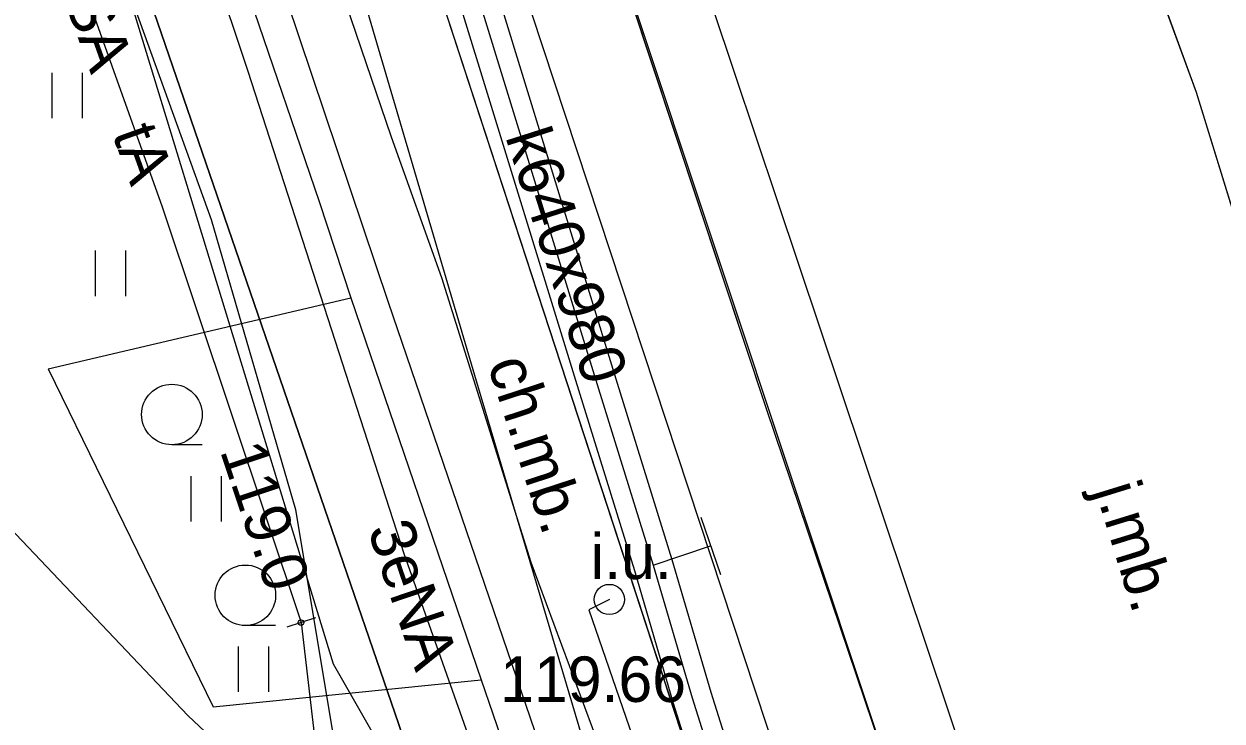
# Model space of a CAD drawing. Extents: x 6432121 to 6432331, y 5662538 to 5662686.
# Drawn here: x 6432255.02 to 6432274.79, y 5662593.95 to 5662605.46 of the extents above; entities that cross this region are included whole.
import ezdxf

# ---------------------------------------------------------------- set-up
doc = ezdxf.new("R2010")
doc.units = 0
for name, color, linetype in [('Warstwa 1', 7, 'Continuous'), ('Warstwa 10', 7, 'Continuous'), ('Warstwa 11', 7, 'Continuous'), ('Warstwa 12', 7, 'Continuous'), ('Warstwa 13', 7, 'Continuous'), ('Warstwa 14', 7, 'Continuous'), ('Warstwa 15', 7, 'Continuous'), ('Warstwa 19', 7, 'Continuous'), ('Warstwa 20', 7, 'Continuous'), ('Warstwa 24', 7, 'Continuous'), ('Warstwa 37', 7, 'Continuous'), ('Warstwa 5', 7, 'Continuous'), ('Warstwa 6', 7, 'Continuous'), ('Warstwa 61', 7, 'Continuous'), ('Warstwa 8', 7, 'Continuous'), ('Warstwa 9', 7, 'Continuous')]:
    doc.layers.add(name, color=color, linetype=linetype)

msp = doc.modelspace()

# ---------------------------------------------------------------- linework, layer by layer
at = {"layer": 'Warstwa 1'}
msp.add_line((6432246.69, 5662636.13), (6432263.163, 5662588.197), dxfattribs=at)
msp.add_line((6432246.69, 5662636.13), (6432263.163, 5662588.197), dxfattribs=at)
at = {"layer": 'Warstwa 10'}
for points in [[(6432244.8, 5662632.18), (6432245.33, 5662629.54), (6432245.69, 5662629.01), (6432246.09, 5662628.79), (6432247.73, 5662627.49), (6432248.93, 5662625.88), (6432257.3, 5662602.44), (6432259.59, 5662595.58)], [(6432259.59, 5662595.58), (6432260.12, 5662591.05), (6432259.44, 5662584.94), (6432258.97, 5662582.4)]]:
    msp.add_lwpolyline(points, dxfattribs=at)
at = {"layer": 'Warstwa 12'}
for points in [[(6432260.149, 5662593.584), (6432259.505, 5662597.442), (6432258.113, 5662602.229), (6432246.261, 5662635.045), (6432242.6, 5662639.91), (6432237.105, 5662644.467), (6432235.235, 5662651.91), (6432228.3, 5662671.335), (6432227.148, 5662676.149), (6432227.614, 5662677.443), (6432228.191, 5662677.996), (6432231.551, 5662678.816), (6432233.235, 5662681.053)], [(6432244.451, 5662661.055), (6432244.51, 5662660.562), (6432244.747, 5662659.597), (6432247.148, 5662651.498), (6432250.159, 5662641.297), (6432254.564, 5662626.481), (6432257.548, 5662616.394), (6432260.807, 5662605.248), (6432262.453, 5662599.664), (6432266.272, 5662586.802), (6432268.265, 5662580.011), (6432268.423, 5662579.446)], [(6432243.958, 5662654.289), (6432246.621, 5662646.365), (6432250.032, 5662636.381), (6432251.998, 5662630.56), (6432253.864, 5662624.956), (6432256.122, 5662618.174), (6432258.071, 5662612.417), (6432261.076, 5662603.597), (6432261.907, 5662601.278), (6432263.382, 5662596.576), (6432264.52, 5662593.503), (6432265.328, 5662591.162), (6432268.156, 5662582.752), (6432268.733, 5662580.715)], [(6432243.16, 5662653.357), (6432252.465, 5662626.114), (6432254.893, 5662619.007), (6432257.883, 5662610.233), (6432261.03, 5662600.869), (6432263.754, 5662592.896), (6432267.107, 5662583.22), (6432267.857, 5662579.356), (6432269.061, 5662572.854)], [(6432244.8, 5662632.18), (6432245.33, 5662629.54), (6432245.69, 5662629.01), (6432246.09, 5662628.79), (6432247.73, 5662627.49), (6432248.93, 5662625.88), (6432257.3, 5662602.44), (6432259.59, 5662595.58)], [(6432249.61, 5662630.185), (6432250.286, 5662629.633), (6432252.331, 5662623.317), (6432254.562, 5662616.419), (6432255.202, 5662614.617), (6432256.008, 5662612.508), (6432256.249, 5662612.065), (6432256.997, 5662609.824), (6432258.713, 5662604.681), (6432261.287, 5662596.72), (6432264.864, 5662586.606), (6432264.777, 5662586.057)], [(6432264.921, 5662586.356), (6432264.864, 5662586.606), (6432260.124, 5662594.894), (6432256.835, 5662605.655), (6432256.691, 5662608.587), (6432255.365, 5662611.413), (6432254.697, 5662614.101), (6432250.901, 5662625.148), (6432249.199, 5662629.099), (6432249.05, 5662629.25)], [(6432262.524, 5662606.965), (6432264.736, 5662599.765), (6432265.711, 5662596.619), (6432266.353, 5662594.428), (6432267.404, 5662591.09), (6432269.38, 5662584.578), (6432270.703, 5662580.126), (6432272.6, 5662573.902), (6432271.988, 5662573.716), (6432270.091, 5662579.942), (6432268.768, 5662584.394), (6432266.792, 5662590.9), (6432265.741, 5662594.242), (6432265.099, 5662596.435), (6432264.124, 5662599.577), (6432261.914, 5662606.769)], [(6432264.68, 5662595.96), (6432264.34, 5662595.79), (6432266.84, 5662588.54), (6432265.25, 5662586.37), (6432264.921, 5662586.356)], [(6432259.59, 5662595.58), (6432260.12, 5662591.05), (6432259.44, 5662584.94), (6432258.97, 5662582.4)]]:
    msp.add_lwpolyline(points, dxfattribs=at)
at = {"layer": 'Warstwa 14'}
msp.add_circle((6432259.59, 5662595.58), 0.045, dxfattribs=at)
at = {"layer": 'Warstwa 19'}
for p, q in [((6432266.192, 5662597.321), (6432266.512, 5662596.374)), ((6432265.405, 5662596.527), (6432266.352, 5662596.847))]:
    msp.add_line(p, q, dxfattribs=at)
at = {"layer": 'Warstwa 20'}
msp.add_line((6432259.827, 5662595.659), (6432259.353, 5662595.501), dxfattribs=at)
msp.add_line((6432259.827, 5662595.659), (6432259.353, 5662595.501), dxfattribs=at)
at = {"layer": 'Warstwa 24'}
msp.add_circle((6432264.68, 5662595.96), 0.25, dxfattribs=at)
at = {"layer": 'Warstwa 37'}
for points in [[(6432270.98, 5662592.032), (6432263.223, 5662615.178), (6432259.09, 5662627.49)], [(6432268.199, 5662591.096), (6432259.533, 5662617.358), (6432256.37, 5662626.58)]]:
    msp.add_lwpolyline(points, dxfattribs=at)
at = {"layer": 'Warstwa 5'}
for p, q in [((6432257.161, 5662610.526), (6432259.889, 5662602.532)), ((6432255.484, 5662603.907), (6432255.484, 5662604.657)), ((6432255.984, 5662603.907), (6432255.984, 5662604.657)), ((6432248.559, 5662603.698), (6432257.724, 5662594.044)), ((6432259.889, 5662602.532), (6432260.414, 5662600.939)), ((6432256.197, 5662600.97), (6432256.197, 5662601.72)), ((6432256.697, 5662600.97), (6432256.697, 5662601.72)), ((6432255.416, 5662599.77), (6432260.414, 5662600.939)), ((6432255.416, 5662599.77), (6432260.414, 5662600.939)), ((6432260.414, 5662600.939), (6432262.563, 5662594.631)), ((6432255.416, 5662599.77), (6432258.141, 5662594.189)), ((6432255.416, 5662599.77), (6432258.141, 5662594.189)), ((6432257.776, 5662597.246), (6432257.776, 5662597.996)), ((6432258.276, 5662597.246), (6432258.276, 5662597.996)), ((6432258.558, 5662594.434), (6432258.558, 5662595.184)), ((6432259.058, 5662594.434), (6432259.058, 5662595.184)), ((6432258.141, 5662594.189), (6432262.563, 5662594.631)), ((6432258.141, 5662594.189), (6432262.563, 5662594.631)), ((6432262.563, 5662594.631), (6432264.041, 5662590.381)), ((6432257.724, 5662594.044), (6432261.011, 5662590.961))]:
    msp.add_line(p, q, dxfattribs=at)
at = {"layer": 'Warstwa 6'}
for p, q in [((6432257.958, 5662598.514), (6432257.458, 5662598.514)), ((6432259.171, 5662595.529), (6432258.671, 5662595.529))]:
    msp.add_line(p, q, dxfattribs=at)
for points in [[(6432295.199, 5662556.053), (6432289.811, 5662577.223), (6432287.64, 5662583.69), (6432267.75, 5662642.76), (6432246.69, 5662636.13), (6432263.163, 5662588.197), (6432269.007, 5662560.534), (6432269.756, 5662556.053)], [(6432261.53, 5662642.45), (6432261.725, 5662641.888), (6432263.054, 5662637.661), (6432266.526, 5662627.159), (6432271.921, 5662611.052), (6432274.366, 5662604.334), (6432277.03, 5662595.697), (6432280.318, 5662586.138), (6432281.64, 5662582.902)], [(6432253.68, 5662630.32), (6432261.638, 5662606.697), (6432266.51, 5662591.804), (6432267.797, 5662587.848)], [(6432257.996, 5662627.099), (6432261.912, 5662615.276), (6432267.276, 5662599.098), (6432269.793, 5662591.641)]]:
    msp.add_lwpolyline(points, dxfattribs=at)
msp.add_lwpolyline([(6432259.074, 5662585.787), (6432263.163, 5662588.197), (6432246.69, 5662636.13), (6432228.29, 5662630.34), (6432193.86, 5662619.79), (6432180.9, 5662615.82)], close=True, dxfattribs=at)
for centre in [(6432257.458, 5662599.014), (6432258.671, 5662596.029)]:
    msp.add_circle(centre, 0.5, dxfattribs=at)
at = {"layer": 'Warstwa 61'}
msp.add_lwpolyline([(6432262.219, 5662606.867), (6432264.43, 5662599.671), (6432265.405, 5662596.527), (6432266.047, 5662594.335), (6432267.098, 5662590.995), (6432269.074, 5662584.486), (6432270.397, 5662580.035), (6432270.397, 5662580.033), (6432272.294, 5662573.809)], dxfattribs=at)
at = {"layer": 'Warstwa 8'}
for p, q in [((6432258.72, 5662624.914), (6432269.793, 5662591.641)), ((6432261.912, 5662615.276), (6432267.276, 5662599.098)), ((6432271.921, 5662611.052), (6432274.366, 5662604.334)), ((6432261.638, 5662606.697), (6432266.51, 5662591.804)), ((6432274.366, 5662604.334), (6432277.03, 5662595.697)), ((6432267.276, 5662599.098), (6432269.793, 5662591.641))]:
    msp.add_line(p, q, dxfattribs=at)
at = {"layer": 'Warstwa 9'}
for p, q in [((6432271.921, 5662611.052), (6432274.366, 5662604.334)), ((6432257.161, 5662610.526), (6432259.889, 5662602.532)), ((6432261.638, 5662606.697), (6432266.51, 5662591.804)), ((6432274.366, 5662604.334), (6432277.03, 5662595.697)), ((6432248.559, 5662603.698), (6432257.724, 5662594.044)), ((6432259.889, 5662602.532), (6432260.414, 5662600.939)), ((6432260.414, 5662600.939), (6432262.563, 5662594.631)), ((6432262.563, 5662594.631), (6432264.041, 5662590.381)), ((6432257.724, 5662594.044), (6432261.011, 5662590.961))]:
    msp.add_line(p, q, dxfattribs=at)

# ---------------------------------------------------------------- texts
at = {"layer": 'Warstwa 11'}
msp.add_text('eSA', height=0.75, rotation=289.6531, dxfattribs=at).set_placement((6432255.489, 5662606.397))
at = {"layer": 'Warstwa 13'}
for s, rotation, p in [('tA', 289.6531, (6432256.469, 5662603.652)), ('k640x980', 287.7738, (6432262.958, 5662603.603)), ('3eNA', 288.6905, (6432260.684, 5662597.118))]:
    msp.add_text(s, height=0.75, rotation=rotation, dxfattribs=at).set_placement(p)
at = {"layer": 'Warstwa 14'}
msp.add_text('119.0', height=0.75, rotation=288.4613, dxfattribs=at).set_placement((6432258.248, 5662598.418))
at = {"layer": 'Warstwa 15'}
msp.add_text('119.66', height=0.75, dxfattribs=at).set_placement((6432262.878, 5662594.269))
at = {"layer": 'Warstwa 24'}
msp.add_text('i.u.', height=0.75, dxfattribs=at).set_placement((6432264.372, 5662596.298))
at = {"layer": 'Warstwa 8'}
msp.add_text('j.mb.', height=0.75, rotation=287.1435, dxfattribs=at).set_placement((6432272.695, 5662597.774))
at = {"layer": 'Warstwa 9'}
msp.add_text('ch.mb.', height=0.75, rotation=288.1118, dxfattribs=at).set_placement((6432262.662, 5662599.846))

doc.saveas('drawing.dxf')
